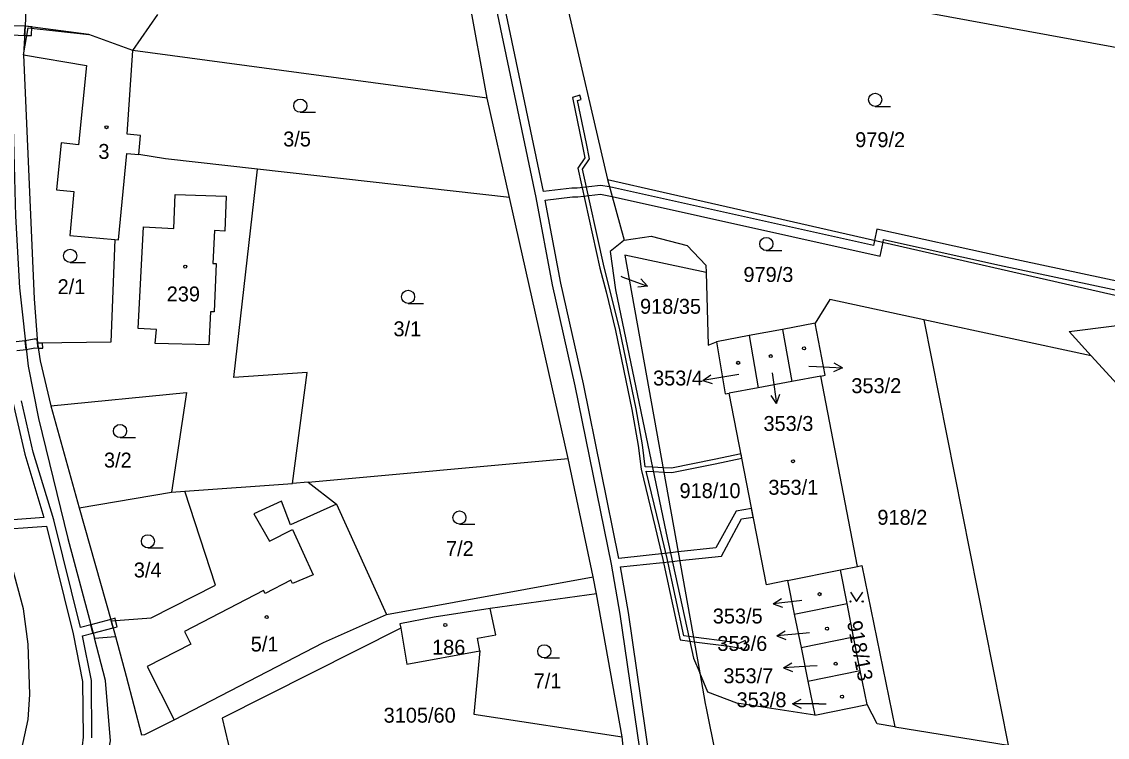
# Model space of a CAD drawing. Extents: x -776734 to -748832, y -1118122 to -976986.
# Drawn here: x -752920 to -752796.2, y -1115444.8 to -1115363.3 of the extents above; entities that cross this region are included whole.
import ezdxf

# ---------------------------------------------------------------- set-up
doc = ezdxf.new("R2010")
doc.units = 0
for name, color, linetype in [('KM_Hranice parcel', 7, 'Continuous'), ('KM_Parcelní čísla', 7, 'Continuous'), ('KM_Pop  PČ popisy', 7, 'Continuous'), ('KM_Vnitřní kresba', 7, 'Continuous'), ('KM_Věcná břemena k části', 7, 'Continuous'), ('KM_Značky budov', 7, 'Continuous'), ('KM_Značky kultur', 7, 'Continuous')]:
    doc.layers.add(name, color=color, linetype=linetype)

msp = doc.modelspace()

# ---------------------------------------------------------------- linework, layer by layer
at = {"layer": 'KM_Hranice parcel'}
for p, q in [((-752866.91, -1115371.98), (-752870.17, -1115354.22)), ((-752859.21, -1115355.44), (-752853.21, -1115381.26)), ((-752829.17, -1115359.94), (-752773.5, -1115370.17)), ((-752907.33, -1115366.55), (-752904.48, -1115362.46)), ((-752919.6, -1115363.76), (-752919.79, -1115367.05)), ((-752866.91, -1115371.98), (-752907.33, -1115366.55)), ((-752864.37, -1115383.3), (-752866.91, -1115371.98)), ((-752864.37, -1115383.3), (-752893.11, -1115380.07)), ((-752853.21, -1115381.26), (-752851.32, -1115388.17)), ((-752857.69, -1115413.05), (-752864.37, -1115383.3)), ((-752841.98, -1115391.86), (-752841.73, -1115400.13)), ((-752829.52, -1115397.61), (-752833.27, -1115398.32)), ((-752798.07, -1115401.33), (-752817.13, -1115397.25)), ((-752817.13, -1115397.25), (-752807.52, -1115445.69)), ((-752837.05, -1115399.04), (-752840.79, -1115399.75)), ((-752833.27, -1115398.32), (-752837.05, -1115399.04)), ((-752837.05, -1115399.04), (-752836.03, -1115404.97)), ((-752833.27, -1115398.32), (-752832.19, -1115404.26)), ((-752841.73, -1115400.13), (-752840.79, -1115399.75)), ((-752788.12, -1115412.23), (-752798.07, -1115401.33)), ((-752828.88, -1115403.65), (-752832.19, -1115404.26)), ((-752824.71, -1115425.34), (-752828.88, -1115403.65)), ((-752836.03, -1115404.97), (-752839.33, -1115405.58)), ((-752832.19, -1115404.26), (-752836.03, -1115404.97)), ((-752916.66, -1115407.05), (-752913.45, -1115418.65)), ((-752887.35, -1115415.74), (-752857.69, -1115413.05)), ((-752854.84, -1115426.53), (-752857.69, -1115413.05)), ((-752901.41, -1115416.76), (-752889.12, -1115415.9)), ((-752887.35, -1115415.74), (-752889.12, -1115415.9)), ((-752913.45, -1115418.65), (-752902.91, -1115416.86)), ((-752902.91, -1115416.86), (-752901.41, -1115416.76)), ((-752913.45, -1115418.65), (-752909.78, -1115431.54)), ((-752832.7, -1115426.95), (-752826.66, -1115425.73)), ((-752826.66, -1115425.73), (-752824.71, -1115425.34)), ((-752825.9, -1115429.56), (-752826.66, -1115425.73)), ((-752878.39, -1115430.83), (-752854.84, -1115426.53)), ((-752854.47, -1115428.47), (-752854.84, -1115426.53)), ((-752832.7, -1115426.95), (-752831.92, -1115430.78)), ((-752854.47, -1115428.47), (-752866.59, -1115430.12)), ((-752851.53, -1115444.76), (-752854.47, -1115428.47)), ((-752831.92, -1115430.78), (-752825.9, -1115429.56)), ((-752825.15, -1115433.37), (-752825.9, -1115429.56)), ((-752831.92, -1115430.78), (-752831.15, -1115434.59)), ((-752909.78, -1115431.54), (-752909.3, -1115433.34)), ((-752911.71, -1115433.53), (-752909.3, -1115433.34)), ((-752831.15, -1115434.59), (-752825.15, -1115433.37)), ((-752824.39, -1115437.21), (-752825.15, -1115433.37)), ((-752831.15, -1115434.59), (-752830.37, -1115438.43)), ((-752843.39, -1115435.79), (-752842.69, -1115437.47)), ((-752830.37, -1115438.43), (-752824.39, -1115437.21)), ((-752823.62, -1115441.07), (-752824.39, -1115437.21)), ((-752830.37, -1115438.43), (-752829.58, -1115442.29)), ((-752829.58, -1115442.29), (-752838.45, -1115440.92)), ((-752829.58, -1115442.29), (-752823.62, -1115441.07)), ((-752822.48, -1115443.27), (-752823.62, -1115441.07)), ((-752820.46, -1115443.6), (-752822.48, -1115443.27)), ((-752820.46, -1115443.6), (-752807.52, -1115445.69)), ((-752851.1, -1115448.69), (-752851.53, -1115444.76))]:
    msp.add_line(p, q, dxfattribs=at)
for points in [[(-752909.15, -1115313.01), (-752912.23, -1115316.65), (-752916.22, -1115328.44), (-752918.31, -1115337.38), (-752919.94, -1115346.18), (-752920.83, -1115354.63), (-752921.19, -1115366.65), (-752920.7, -1115385.42), (-752920.25, -1115393.58), (-752919.26, -1115402.52), (-752918.06, -1115408.48), (-752914.75, -1115422.15), (-752911.71, -1115433.53)], [(-752917.01, -1115339.87), (-752917.67, -1115343.26), (-752918.38, -1115347.45), (-752918.89, -1115351.68), (-752919.35, -1115358.21), (-752919.6, -1115363.76)], [(-752907.33, -1115366.55), (-752912.33, -1115364.74), (-752919.6, -1115363.76)], [(-752906.65, -1115378.41), (-752906.45, -1115376.22), (-752907.95, -1115376.09), (-752907.33, -1115366.55)], [(-752919.79, -1115367.05), (-752912.62, -1115368.26), (-752913.51, -1115377.3), (-752915.51, -1115377.05), (-752916.02, -1115382.43), (-752914.03, -1115382.63), (-752914.52, -1115387.62), (-752909.37, -1115388.07)], [(-752919.79, -1115367.05), (-752918.57, -1115394.86), (-752918.19, -1115399.91)], [(-752909.37, -1115388.07), (-752908.97, -1115388.11), (-752907.99, -1115378.29), (-752906.65, -1115378.41)], [(-752893.11, -1115380.07), (-752903.59, -1115378.89), (-752906.65, -1115378.41)], [(-752889.12, -1115415.9), (-752887.44, -1115403.23), (-752895.79, -1115403.81), (-752893.11, -1115380.07)], [(-752853.21, -1115381.26), (-752834.18, -1115385.59), (-752785.51, -1115396.65)], [(-752851.32, -1115388.17), (-752848.25, -1115387.7), (-752844.13, -1115388.75), (-752842, -1115391.02), (-752841.98, -1115391.86)], [(-752909.37, -1115388.07), (-752909.84, -1115399.79), (-752918.19, -1115399.91)], [(-752851.32, -1115388.17), (-752851.56, -1115388.37), (-752852.92, -1115389.46), (-752852.28, -1115393.8)], [(-752841.98, -1115391.86), (-752851.22, -1115389.86), (-752842.69, -1115437.47)], [(-752852.28, -1115393.8), (-752846.52, -1115421.54), (-752843.39, -1115435.79)], [(-752817.13, -1115397.25), (-752827.86, -1115394.92), (-752829.52, -1115397.61)], [(-752828.88, -1115403.65), (-752828.39, -1115403.56), (-752829.52, -1115397.61)], [(-752798.07, -1115401.33), (-752800.58, -1115398.58), (-752785.51, -1115396.65)], [(-752918.19, -1115399.91), (-752917.89, -1115401.9), (-752916.66, -1115407.05)], [(-752840.79, -1115399.75), (-752839.8, -1115405.66), (-752839.33, -1115405.58)], [(-752916.66, -1115407.05), (-752901.2, -1115405.53), (-752902.91, -1115416.86)], [(-752832.7, -1115426.95), (-752835.1, -1115427.44), (-752839.33, -1115405.58)], [(-752887.35, -1115415.74), (-752884.09, -1115418.23), (-752878.39, -1115430.83)], [(-752909.78, -1115431.54), (-752905.24, -1115431.2), (-752897.91, -1115427.47), (-752901.41, -1115416.76)], [(-752929.49, -1115483.81), (-752928.23, -1115483.83), (-752919.26, -1115442.77), (-752919.07, -1115439.94), (-752919.26, -1115434.19), (-752919.8, -1115430.15), (-752921.44, -1115423.97), (-752922.78, -1115423.28)], [(-752824.71, -1115425.34), (-752824.23, -1115425.24), (-752820.46, -1115443.6)], [(-752909.3, -1115433.34), (-752908.1, -1115437.86), (-752906.33, -1115444.54), (-752905.97, -1115444.47), (-752902.61, -1115442.81), (-752885.57, -1115434.02), (-752878.39, -1115430.83)], [(-752866.59, -1115430.12), (-752872.97, -1115431.12), (-752876.87, -1115431.86), (-752876.78, -1115432.38)], [(-752867.76, -1115434.94), (-752868.02, -1115433.52), (-752865.93, -1115433.14), (-752866.59, -1115430.12)], [(-752876.78, -1115432.38), (-752897.15, -1115442.62), (-752896.13, -1115446.97)], [(-752876.78, -1115432.38), (-752876.09, -1115436.47), (-752867.76, -1115434.94)], [(-752910.48, -1115454.47), (-752911.54, -1115454.11), (-752909.87, -1115445.21), (-752910.42, -1115438.34), (-752911.71, -1115433.53)], [(-752867.76, -1115434.94), (-752868.43, -1115442.16), (-752851.53, -1115444.76)], [(-752838.45, -1115440.92), (-752841.78, -1115439.68), (-752842.69, -1115437.47)], [(-752842.69, -1115437.47), (-752842.07, -1115440.97), (-752841.97, -1115441.47), (-752839.87, -1115451.84)]]:
    msp.add_lwpolyline(points, dxfattribs=at)
at = {"layer": 'KM_Pop  PČ popisy'}
for p, q in [((-752851.68, -1115392.28), (-752851.46, -1115392.36)), ((-752851.46, -1115392.36), (-752848.64, -1115393.386)), ((-752848.64, -1115393.386), (-752849.41, -1115392.573)), ((-752848.64, -1115393.386), (-752849.752, -1115393.514)), ((-752830.26, -1115402.51), (-752829.4, -1115402.56)), ((-752829.4, -1115402.56), (-752826.403, -1115402.717)), ((-752826.403, -1115402.717), (-752827.429, -1115403.165)), ((-752826.403, -1115402.717), (-752827.377, -1115402.165)), ((-752842.344, -1115404.139), (-752841.433, -1115403.488)), ((-752839.38, -1115403.67), (-752842.344, -1115404.139)), ((-752838.22, -1115403.48), (-752839.38, -1115403.67)), ((-752834.42, -1115403.29), (-752834.35, -1115403.8)), ((-752834.35, -1115403.8), (-752833.932, -1115406.772)), ((-752842.344, -1115404.139), (-752841.277, -1115404.477)), ((-752833.932, -1115406.772), (-752834.568, -1115405.85)), ((-752833.932, -1115406.772), (-752833.576, -1115405.71)), ((-752834.309, -1115429.606), (-752833.376, -1115428.987)), ((-752831.33, -1115429.24), (-752834.309, -1115429.606)), ((-752834.309, -1115429.606), (-752833.254, -1115429.981)), ((-752831.04, -1115429.21), (-752831.33, -1115429.24)), ((-752833.92, -1115433.252), (-752832.966, -1115432.665)), ((-752830.93, -1115432.99), (-752833.92, -1115433.252)), ((-752833.92, -1115433.252), (-752832.878, -1115433.663)), ((-752830.17, -1115432.92), (-752830.93, -1115432.99)), ((-752833.157, -1115436.877), (-752832.183, -1115436.325)), ((-752830.16, -1115436.72), (-752833.157, -1115436.877)), ((-752833.157, -1115436.877), (-752832.131, -1115437.325)), ((-752829.3, -1115436.67), (-752830.16, -1115436.72)), ((-752832.121, -1115440.98), (-752831.12, -1115440.479)), ((-752829.12, -1115440.98), (-752832.121, -1115440.98)), ((-752832.121, -1115440.98), (-752831.12, -1115441.481)), ((-752829.12, -1115440.98), (-752828.3, -1115440.98))]:
    msp.add_line(p, q, dxfattribs=at)
at = {"layer": 'KM_Vnitřní kresba'}
for p, q in [((-752919.79, -1115367.05), (-752919.27, -1115363.96)), ((-752919.27, -1115363.96), (-752912.33, -1115364.74)), ((-752902.65, -1115386.83), (-752902.48, -1115382.97)), ((-752902.48, -1115382.97), (-752896.69, -1115383.15)), ((-752896.69, -1115383.15), (-752896.83, -1115387.12)), ((-752906.72, -1115398.23), (-752906.12, -1115386.65)), ((-752906.12, -1115386.65), (-752902.65, -1115386.83)), ((-752898.03, -1115387.06), (-752898.21, -1115390.8)), ((-752896.83, -1115387.12), (-752898.03, -1115387.06)), ((-752898.21, -1115390.8), (-752897.81, -1115390.82)), ((-752897.81, -1115390.82), (-752898.06, -1115396.33)), ((-752898.47, -1115396.31), (-752898.64, -1115400.1)), ((-752898.06, -1115396.33), (-752898.47, -1115396.31)), ((-752904.62, -1115398.34), (-752906.72, -1115398.23)), ((-752904.77, -1115399.93), (-752904.62, -1115398.34)), ((-752898.64, -1115400.1), (-752904.77, -1115399.93)), ((-752890.37, -1115417.91), (-752893.53, -1115419.34)), ((-752889.36, -1115420.61), (-752890.37, -1115417.91)), ((-752884.09, -1115418.23), (-752889.36, -1115420.61)), ((-752893.53, -1115419.34), (-752891.75, -1115422.46)), ((-752891.75, -1115422.46), (-752889.11, -1115421.12)), ((-752889.11, -1115421.12), (-752886.77, -1115426.29)), ((-752886.77, -1115426.29), (-752889.12, -1115427.27)), ((-752889.31, -1115426.9), (-752892.24, -1115428.43)), ((-752889.12, -1115427.27), (-752889.31, -1115426.9)), ((-752892.41, -1115428.09), (-752901.44, -1115432.74)), ((-752892.24, -1115428.43), (-752892.41, -1115428.09)), ((-752901.44, -1115432.74), (-752900.7, -1115434.19)), ((-752900.7, -1115434.19), (-752905.69, -1115436.74)), ((-752905.69, -1115436.74), (-752902.61, -1115442.81))]:
    msp.add_line(p, q, dxfattribs=at)
at = {"layer": 'KM_Věcná břemena k části'}
for points in [[(-752909.81, -1115301.41), (-752913.21, -1115312.44), (-752917.81, -1115311.12), (-752918.13, -1115312.07), (-752913.53, -1115313.38), (-752918.1, -1115327.36), (-752920.78, -1115338.33), (-752921.85, -1115344.12), (-752922.81, -1115351.85), (-752923.19, -1115358.59), (-752923.19, -1115364.19), (-752922.39, -1115390.26), (-752921.6, -1115400.36), (-752920.99, -1115406.6), (-752919.65, -1115412.55), (-752917.46, -1115419.75), (-752924.02, -1115420.24), (-752923.62, -1115421.21), (-752917.18, -1115420.74), (-752914.12, -1115433.02), (-752913.05, -1115438.46), (-752912.99, -1115444.8), (-752913.22, -1115446.77)], [(-752787.48, -1115394.46), (-752808.33, -1115390.02), (-752822.51, -1115386.89), (-752822.78, -1115388.18), (-752822.9, -1115388.78), (-752852.98, -1115382.09), (-752854, -1115381.93), (-752856.65, -1115382.22), (-752857.27, -1115382.22), (-752860.5, -1115382.62), (-752867.2, -1115350.72), (-752868.55, -1115343.51), (-752863.67, -1115342.72), (-752862.82, -1115342.45), (-752863.02, -1115341.47), (-752863.9, -1115341.74), (-752868.74, -1115342.53), (-752869.74, -1115337.96), (-752871.82, -1115327.94), (-752874.68, -1115317.86), (-752874.95, -1115315.89), (-752875.52, -1115311.65), (-752875.53, -1115306.11)], [(-752868.2, -1115350.85), (-752861.39, -1115383.28), (-752859.53, -1115393.26), (-752856.92, -1115404.77), (-752852.79, -1115425.08), (-752851.8, -1115430.77), (-752849.3, -1115447.98)], [(-752848.37, -1115447.41), (-752850.81, -1115430.6), (-752851.72, -1115425.4), (-752845.81, -1115424.76), (-752844.99, -1115424.67), (-752840.23, -1115424.15), (-752837.92, -1115419.93), (-752836.6, -1115419.71), (-752836.79, -1115418.74), (-752838.56, -1115419.03), (-752840.85, -1115423.21), (-752845.16, -1115423.68), (-752846.03, -1115423.78), (-752851.9, -1115424.42), (-752855.94, -1115404.54), (-752858.54, -1115393.07), (-752860.31, -1115383.6), (-752857.21, -1115383.22), (-752856.59, -1115383.22), (-752854.02, -1115382.93), (-752852.69, -1115383.18), (-752822.13, -1115389.98), (-752821.8, -1115388.4), (-752821.74, -1115388.09), (-752808.51, -1115391), (-752787.45, -1115395.48)], [(-752920.55, -1115400.75), (-752919.47, -1115400.62), (-752919.58, -1115399.62), (-752920.64, -1115399.76)], [(-752911.99, -1115444.86), (-752912.05, -1115438.35), (-752913.05, -1115433.26), (-752911.87, -1115432.95), (-752912.12, -1115431.99), (-752913.27, -1115432.29), (-752916.32, -1115420.03), (-752918.69, -1115412.3), (-752920, -1115406.45)]]:
    msp.add_lwpolyline(points, dxfattribs=at)
for points in [[(-752919.6, -1115363.76), (-752921.1, -1115363.73), (-752921.13, -1115364.75), (-752919.66, -1115364.82)], [(-752919.6, -1115363.76), (-752919.66, -1115364.82), (-752918.87, -1115364.85), (-752918.83, -1115363.86)], [(-752837.52, -1115433.77), (-752838.25, -1115434.11), (-752839.26, -1115433.94), (-752843.42, -1115433.4), (-752843.93, -1115433.33), (-752844.49, -1115433.26), (-752846.42, -1115424.42), (-752847.28, -1115420.75), (-752848.82, -1115414.48), (-752847.98, -1115414.53), (-752846.79, -1115414.6), (-752845.87, -1115414.65), (-752840.94, -1115413.65), (-752837.89, -1115413.01), (-752837.99, -1115412.51), (-752841.04, -1115413.17), (-752845.91, -1115414.15), (-752846.88, -1115414.09), (-752848.08, -1115414.02), (-752848.92, -1115413.97), (-752849.23, -1115411.49), (-752849.95, -1115407.37), (-752851.82, -1115398.37), (-752852.9, -1115393.94), (-752853.6, -1115391.23), (-752856.07, -1115380.05), (-752855.27, -1115378.91), (-752855.6, -1115377.15), (-752856.62, -1115372.25), (-752856.22, -1115372.13), (-752856.36, -1115371.65), (-752857.2, -1115371.89), (-752856.1, -1115377.25), (-752855.81, -1115378.79), (-752856.61, -1115379.95), (-752854.08, -1115391.35), (-752853.38, -1115394.06), (-752852.3, -1115398.47), (-752850.45, -1115407.47), (-752849.73, -1115411.57), (-752849.39, -1115414.26), (-752847.76, -1115420.87), (-752846.9, -1115424.54), (-752844.91, -1115433.7), (-752843.82, -1115433.85), (-752843.33, -1115433.91), (-752839.34, -1115434.44), (-752838.26, -1115434.61), (-752837.62, -1115434.79), (-752837.37, -1115434.47), (-752837.31, -1115434.22)], [(-752918.11, -1115400.46), (-752918.19, -1115399.91), (-752918.22, -1115399.45), (-752918.58, -1115399.44), (-752919.58, -1115399.62), (-752919.47, -1115400.62), (-752918.5, -1115400.44)], [(-752918.19, -1115399.91), (-752918.11, -1115400.46), (-752917.6, -1115400.45), (-752917.61, -1115399.9)], [(-752909.83, -1115431.38), (-752909.78, -1115431.54), (-752909.57, -1115432.34), (-752909.09, -1115432.22), (-752909.28, -1115431.5), (-752909.35, -1115431.25)], [(-752909.57, -1115432.34), (-752909.83, -1115431.38), (-752912.12, -1115431.99), (-752911.87, -1115432.95)]]:
    msp.add_lwpolyline(points, close=True, dxfattribs=at)
at = {"layer": 'KM_Značky budov'}
for centre in [(-752910.3268, -1115375.2892), (-752901.3468, -1115391.1692), (-752830.8068, -1115400.4892), (-752834.5968, -1115401.3692), (-752838.3168, -1115402.1392), (-752832.0568, -1115413.3492), (-752829.0368, -1115428.4992), (-752892.0568, -1115431.1092), (-752871.6968, -1115432.0192), (-752828.1768, -1115432.4292), (-752827.1968, -1115436.4292), (-752826.4668, -1115440.1792)]:
    msp.add_circle(centre, 0.175, dxfattribs=at)
at = {"layer": 'KM_Značky kultur'}
for p, q in [((-752822.703, -1115372.91), (-752820.953, -1115372.91)), ((-752888.233, -1115373.59), (-752886.483, -1115373.59)), ((-752835.103, -1115389.34), (-752833.353, -1115389.34)), ((-752914.463, -1115390.7), (-752912.713, -1115390.7)), ((-752875.943, -1115395.36), (-752874.193, -1115395.36)), ((-752908.783, -1115410.66), (-752907.033, -1115410.66)), ((-752870.093, -1115420.52), (-752868.343, -1115420.52)), ((-752905.603, -1115423.22), (-752903.853, -1115423.22)), ((-752860.413, -1115435.76), (-752858.663, -1115435.76))]:
    msp.add_line(p, q, dxfattribs=at)
msp.add_lwpolyline([(-752825.51, -1115428.279), (-752824.81, -1115429.33), (-752824.11, -1115428.279)], dxfattribs=at)
for centre, radius in [((-752822.7029, -1115372.1598), 0.75), ((-752888.2329, -1115372.8398), 0.75), ((-752835.1029, -1115388.5898), 0.75), ((-752914.4629, -1115389.9498), 0.75), ((-752875.9429, -1115394.6098), 0.75), ((-752908.7829, -1115409.9098), 0.75), ((-752870.0929, -1115419.7698), 0.75), ((-752905.6029, -1115422.4698), 0.75), ((-752825.51, -1115429.3296), 0.07), ((-752824.11, -1115429.3296), 0.07), ((-752860.4129, -1115435.0098), 0.75)]:
    msp.add_circle(centre, radius, dxfattribs=at)

# ---------------------------------------------------------------- texts
at = {"layer": 'KM_Parcelní čísla'}
for s, p in [('3/5', (-752890.18, -1115377.48)), ('979/2', (-752824.97, -1115377.56)), ('3', (-752911.25, -1115378.9)), ('979/3', (-752837.71, -1115392.92)), ('2/1', (-752915.9, -1115394.31)), ('239', (-752903.46, -1115395.14)), ('918/35', (-752849.5, -1115396.548)), ('3/1', (-752877.61, -1115399.11)), ('353/4', (-752848.017, -1115404.718)), ('353/2', (-752825.41, -1115405.588)), ('353/3', (-752835.43, -1115409.898)), ('3/2', (-752910.61, -1115414.07)), ('918/10', (-752845, -1115417.55)), ('353/1', (-752834.87, -1115417.17)), ('918/2', (-752822.44, -1115420.59)), ('7/2', (-752871.62, -1115424.15)), ('3/4', (-752907.21, -1115426.59)), ('353/5', (-752841.207, -1115431.838)), ('5/1', (-752893.88, -1115435.03)), ('186', (-752873.21, -1115435.39)), ('353/6', (-752840.687, -1115434.968)), ('7/1', (-752861.62, -1115439.23)), ('353/7', (-752839.997, -1115438.648)), ('353/8', (-752838.497, -1115441.38)), ('3105/60', (-752878.73, -1115443.14))]:
    msp.add_text(s, height=1.7, dxfattribs=at).set_placement(p)
msp.add_text('918/13', height=1.7, rotation=281, dxfattribs=at).set_placement((-752825.914, -1115431.692))

doc.saveas('drawing.dxf')
